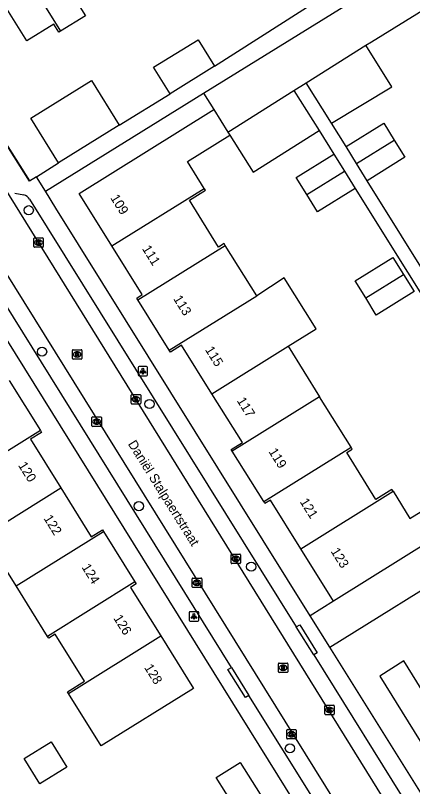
# Model space of a CAD drawing. Extents: x 159353 to 160616, y 385893 to 387321.
# Drawn here: x 159691.4 to 159733.4, y 385945.7 to 386027.3 of the extents above; entities that cross this region are included whole.
import ezdxf

# ---------------------------------------------------------------- set-up
doc = ezdxf.new("R2010")
doc.units = 0
for name, color, linetype in [('IMGEO_Boom', 7, 'Continuous'), ('IMGEO_Kolk', 7, 'Continuous'), ('IMGEO_Lichtpunt', 7, 'Continuous'), ('IMGEO_Muur', 7, 'Continuous'), ('IMGEO_Openbare_ruimte_label', 7, 'Continuous'), ('IMGEO_Pand', 7, 'Continuous'), ('IMGEO_Pand_nummerreeks', 7, 'Continuous'), ('IMGEO_Parkeervlak_open', 7, 'Continuous'), ('IMGEO_Rijbaan_lokaal_open', 7, 'Continuous'), ('IMGEO_Rioolput', 7, 'Continuous'), ('IMGEO_Voetpad_open', 7, 'Continuous')]:
    doc.layers.add(name, color=color, linetype=linetype)

msp = doc.modelspace()

# ---------------------------------------------------------------- linework, layer by layer
at = {"layer": 'IMGEO_Boom'}
for centre in [(159692.77, 386006.677), (159694.18, 385991.71), (159705.547, 385986.176), (159704.42, 385975.36), (159716.313, 385968.957), (159720.412, 385949.728)]:
    msp.add_circle(centre, 0.489, dxfattribs=at)
at = {"layer": 'IMGEO_Kolk'}
for p, q in [((159693.312, 386002.831), (159693.312, 386003.683)), ((159693.387, 386003.757), (159694.239, 386003.757)), ((159694.313, 386003.683), (159694.313, 386002.831)), ((159693.823, 386002.977), (159693.798, 386002.977)), ((159693.8, 386003.537), (159693.825, 386003.537)), ((159694.239, 386002.757), (159693.387, 386002.757)), ((159703.619, 385986.245), (159703.619, 385987.097)), ((159703.694, 385987.171), (159704.546, 385987.171)), ((159704.107, 385986.951), (159704.132, 385986.951)), ((159704.62, 385987.097), (159704.62, 385986.245)), ((159704.546, 385986.171), (159703.694, 385986.171)), ((159704.13, 385986.391), (159704.105, 385986.391)), ((159699.461, 385983.876), (159699.461, 385984.728)), ((159699.536, 385984.802), (159700.388, 385984.802)), ((159699.949, 385984.582), (159699.974, 385984.582)), ((159700.462, 385984.728), (159700.462, 385983.876)), ((159700.388, 385983.802), (159699.536, 385983.802)), ((159699.972, 385984.022), (159699.947, 385984.022)), ((159714.18, 385969.359), (159714.18, 385970.211)), ((159714.255, 385970.285), (159715.107, 385970.285)), ((159715.181, 385970.211), (159715.181, 385969.359)), ((159714.691, 385969.505), (159714.666, 385969.505)), ((159714.668, 385970.065), (159714.693, 385970.065)), ((159715.107, 385969.285), (159714.255, 385969.285)), ((159710.071, 385966.826), (159710.071, 385967.678)), ((159710.146, 385967.752), (159710.998, 385967.752)), ((159710.582, 385966.972), (159710.557, 385966.972)), ((159710.559, 385967.532), (159710.584, 385967.532)), ((159711.072, 385967.678), (159711.072, 385966.826)), ((159710.998, 385966.752), (159710.146, 385966.752)), ((159724.102, 385953.364), (159724.102, 385954.216)), ((159724.177, 385954.29), (159725.029, 385954.29)), ((159724.59, 385954.07), (159724.615, 385954.07)), ((159725.103, 385954.216), (159725.103, 385953.364)), ((159725.029, 385953.29), (159724.177, 385953.29)), ((159724.613, 385953.51), (159724.588, 385953.51)), ((159720.067, 385950.797), (159720.067, 385951.649)), ((159720.142, 385951.723), (159720.994, 385951.723)), ((159720.555, 385951.503), (159720.58, 385951.503)), ((159721.068, 385951.649), (159721.068, 385950.797)), ((159720.994, 385950.723), (159720.142, 385950.723)), ((159720.578, 385950.943), (159720.553, 385950.943))]:
    msp.add_line(p, q, dxfattribs=at)
for points in [[(159693.312, 386002.831), (159693.312, 386003.683)], [(159693.387, 386003.757), (159694.239, 386003.757)], [(159694.313, 386003.683), (159694.313, 386002.831)], [(159693.633, 386003.457), (159693.756, 386003.457), (159693.756, 386003.306), (159693.886, 386003.457), (159694.05, 386003.457), (159693.904, 386003.306), (159694.057, 386003.057), (159693.905, 386003.057), (159693.82, 386003.221), (159693.756, 386003.154), (159693.756, 386003.057), (159693.633, 386003.057), (159693.633, 386003.457)], [(159694.239, 386002.757), (159693.387, 386002.757)], [(159703.619, 385986.245), (159703.619, 385987.097)], [(159703.694, 385987.171), (159704.546, 385987.171)], [(159703.94, 385986.871), (159704.063, 385986.871), (159704.063, 385986.72), (159704.193, 385986.871), (159704.357, 385986.871), (159704.211, 385986.72), (159704.364, 385986.471), (159704.212, 385986.471), (159704.127, 385986.635), (159704.063, 385986.568), (159704.063, 385986.471), (159703.94, 385986.471), (159703.94, 385986.871)], [(159704.62, 385987.097), (159704.62, 385986.245)], [(159704.546, 385986.171), (159703.694, 385986.171)], [(159699.461, 385983.876), (159699.461, 385984.728)], [(159699.536, 385984.802), (159700.388, 385984.802)], [(159699.782, 385984.502), (159699.905, 385984.502), (159699.905, 385984.351), (159700.035, 385984.502), (159700.199, 385984.502), (159700.053, 385984.351), (159700.206, 385984.102), (159700.054, 385984.102), (159699.969, 385984.266), (159699.905, 385984.199), (159699.905, 385984.102), (159699.782, 385984.102), (159699.782, 385984.502)], [(159700.462, 385984.728), (159700.462, 385983.876)], [(159700.388, 385983.802), (159699.536, 385983.802)], [(159714.18, 385969.359), (159714.18, 385970.211)], [(159714.255, 385970.285), (159715.107, 385970.285)], [(159715.181, 385970.211), (159715.181, 385969.359)], [(159714.501, 385969.985), (159714.624, 385969.985), (159714.624, 385969.834), (159714.754, 385969.985), (159714.918, 385969.985), (159714.772, 385969.834), (159714.925, 385969.585), (159714.773, 385969.585), (159714.688, 385969.749), (159714.624, 385969.682), (159714.624, 385969.585), (159714.501, 385969.585), (159714.501, 385969.985)], [(159715.107, 385969.285), (159714.255, 385969.285)], [(159710.071, 385966.826), (159710.071, 385967.678)], [(159710.146, 385967.752), (159710.998, 385967.752)], [(159710.392, 385967.452), (159710.515, 385967.452), (159710.515, 385967.301), (159710.645, 385967.452), (159710.809, 385967.452), (159710.663, 385967.301), (159710.816, 385967.052), (159710.664, 385967.052), (159710.579, 385967.216), (159710.515, 385967.149), (159710.515, 385967.052), (159710.392, 385967.052), (159710.392, 385967.452)], [(159711.072, 385967.678), (159711.072, 385966.826)], [(159710.998, 385966.752), (159710.146, 385966.752)], [(159724.102, 385953.364), (159724.102, 385954.216)], [(159724.177, 385954.29), (159725.029, 385954.29)], [(159724.423, 385953.99), (159724.546, 385953.99), (159724.546, 385953.839), (159724.676, 385953.99), (159724.84, 385953.99), (159724.694, 385953.839), (159724.847, 385953.59), (159724.695, 385953.59), (159724.61, 385953.754), (159724.546, 385953.687), (159724.546, 385953.59), (159724.423, 385953.59), (159724.423, 385953.99)], [(159725.103, 385954.216), (159725.103, 385953.364)], [(159725.029, 385953.29), (159724.177, 385953.29)], [(159720.067, 385950.797), (159720.067, 385951.649)], [(159720.142, 385951.723), (159720.994, 385951.723)], [(159721.068, 385951.649), (159721.068, 385950.797)], [(159720.994, 385950.723), (159720.142, 385950.723)], [(159720.388, 385951.423), (159720.511, 385951.423), (159720.511, 385951.272), (159720.641, 385951.423), (159720.805, 385951.423), (159720.659, 385951.272), (159720.812, 385951.023), (159720.66, 385951.023), (159720.575, 385951.187), (159720.511, 385951.12), (159720.511, 385951.023), (159720.388, 385951.023), (159720.388, 385951.423)]]:
    msp.add_lwpolyline(points, dxfattribs=at)
for centre, start, end in [((159693.389, 386003.681), 91.55205, 178.44795), ((159693.389, 386003.681), 91.55205, 178.44795), ((159694.237, 386003.681), 1.55205, 88.44795), ((159694.237, 386003.681), 1.55205, 88.44795), ((159693.389, 386002.833), 181.55205, 268.44795), ((159693.389, 386002.833), 181.55205, 268.44795), ((159694.237, 386002.833), 271.55205, 358.44795), ((159694.237, 386002.833), 271.55205, 358.44795), ((159703.696, 385987.095), 91.55205, 178.44795), ((159703.696, 385987.095), 91.55205, 178.44795), ((159704.544, 385987.095), 1.55205, 88.44795), ((159704.544, 385987.095), 1.55205, 88.44795), ((159703.696, 385986.247), 181.55205, 268.44795), ((159703.696, 385986.247), 181.55205, 268.44795), ((159704.544, 385986.247), 271.55205, 358.44795), ((159704.544, 385986.247), 271.55205, 358.44795), ((159699.538, 385984.726), 91.55205, 178.44795), ((159699.538, 385984.726), 91.55205, 178.44795), ((159700.386, 385984.726), 1.55205, 88.44795), ((159700.386, 385984.726), 1.55205, 88.44795), ((159699.538, 385983.878), 181.55205, 268.44795), ((159699.538, 385983.878), 181.55205, 268.44795), ((159700.386, 385983.878), 271.55205, 358.44795), ((159700.386, 385983.878), 271.55205, 358.44795), ((159714.257, 385970.209), 91.55205, 178.44795), ((159714.257, 385970.209), 91.55205, 178.44795), ((159715.105, 385970.209), 1.55205, 88.44795), ((159715.105, 385970.209), 1.55205, 88.44795), ((159714.257, 385969.361), 181.55205, 268.44795), ((159714.257, 385969.361), 181.55205, 268.44795), ((159715.105, 385969.361), 271.55205, 358.44795), ((159715.105, 385969.361), 271.55205, 358.44795), ((159710.148, 385967.676), 91.55205, 178.44795), ((159710.148, 385967.676), 91.55205, 178.44795), ((159710.996, 385967.676), 1.55205, 88.44795), ((159710.996, 385967.676), 1.55205, 88.44795), ((159710.148, 385966.828), 181.55205, 268.44795), ((159710.148, 385966.828), 181.55205, 268.44795), ((159710.996, 385966.828), 271.55205, 358.44795), ((159710.996, 385966.828), 271.55205, 358.44795), ((159724.179, 385954.214), 91.55205, 178.44795), ((159724.179, 385954.214), 91.55205, 178.44795), ((159725.027, 385954.214), 1.55205, 88.44795), ((159725.027, 385954.214), 1.55205, 88.44795), ((159724.179, 385953.366), 181.55205, 268.44795), ((159724.179, 385953.366), 181.55205, 268.44795), ((159725.027, 385953.366), 271.55205, 358.44795), ((159725.027, 385953.366), 271.55205, 358.44795), ((159720.144, 385951.647), 91.55205, 178.44795), ((159720.144, 385951.647), 91.55205, 178.44795), ((159720.992, 385951.647), 1.55205, 88.44795), ((159720.992, 385951.647), 1.55205, 88.44795), ((159720.144, 385950.799), 181.55205, 268.44795), ((159720.144, 385950.799), 181.55205, 268.44795), ((159720.992, 385950.799), 271.55205, 358.44795), ((159720.992, 385950.799), 271.55205, 358.44795)]:
    msp.add_arc(centre, 0.0765, start, end, dxfattribs=at)
for centre, major_axis, ratio, start_param, end_param in [((159693.799, 386003.257), (-0.387, 0.002), 0.722429, 4.712389, 7.853982), ((159693.824, 386003.257), (-0.39, 0.002), 0.717154, 1.570796, 4.712389), ((159704.106, 385986.671), (-0.387, 0.002), 0.722429, 4.712389, 7.853982), ((159704.131, 385986.671), (-0.39, 0.002), 0.717154, 1.570796, 4.712389), ((159699.948, 385984.302), (-0.387, 0.002), 0.722429, 4.712389, 7.853982), ((159699.973, 385984.302), (-0.39, 0.002), 0.717154, 1.570796, 4.712389), ((159714.667, 385969.785), (-0.387, 0.002), 0.722429, 4.712389, 7.853982), ((159714.692, 385969.785), (-0.39, 0.002), 0.717154, 1.570796, 4.712389), ((159710.558, 385967.252), (-0.387, 0.002), 0.722429, 4.712389, 7.853982), ((159710.583, 385967.252), (-0.39, 0.002), 0.717154, 1.570796, 4.712389), ((159724.589, 385953.79), (-0.387, 0.002), 0.722429, 4.712389, 7.853982), ((159724.614, 385953.79), (-0.39, 0.002), 0.717154, 1.570796, 4.712389), ((159720.554, 385951.223), (-0.387, 0.002), 0.722429, 4.712389, 7.853982), ((159720.579, 385951.223), (-0.39, 0.002), 0.717154, 1.570796, 4.712389)]:
    msp.add_ellipse(centre, major_axis=major_axis, ratio=ratio, start_param=start_param, end_param=end_param, dxfattribs=at)
at = {"layer": 'IMGEO_Lichtpunt'}
for p, q in [((159704.345, 385990.054), (159704.345, 385989.247)), ((159704.345, 385990.054), (159704.345, 385989.247)), ((159705.247, 385990.149), (159704.439, 385990.149)), ((159705.247, 385990.149), (159704.439, 385990.149)), ((159705.341, 385989.247), (159705.341, 385990.054)), ((159705.341, 385989.247), (159705.341, 385990.054)), ((159704.439, 385989.153), (159705.247, 385989.153)), ((159704.439, 385989.153), (159705.247, 385989.153)), ((159709.758, 385964.093), (159709.758, 385963.286)), ((159709.758, 385964.093), (159709.758, 385963.286)), ((159710.66, 385964.188), (159709.852, 385964.188)), ((159710.66, 385964.188), (159709.852, 385964.188)), ((159710.754, 385963.286), (159710.754, 385964.093)), ((159710.754, 385963.286), (159710.754, 385964.093)), ((159709.852, 385963.192), (159710.66, 385963.192)), ((159709.852, 385963.192), (159710.66, 385963.192))]:
    msp.add_line(p, q, dxfattribs=at)
for points in [[(159704.719, 385989.718), (159704.758, 385989.69), (159704.57, 385989.428), (159704.532, 385989.455), (159704.719, 385989.718)], [(159704.821, 385989.67), (159704.868, 385989.67), (159704.868, 385989.348), (159704.821, 385989.348), (159704.821, 385989.67)], [(159704.931, 385989.69), (159704.969, 385989.717), (159705.156, 385989.455), (159705.117, 385989.427), (159704.931, 385989.69)], [(159710.132, 385963.757), (159710.171, 385963.729), (159709.983, 385963.467), (159709.945, 385963.494), (159710.132, 385963.757)], [(159710.234, 385963.709), (159710.281, 385963.709), (159710.281, 385963.387), (159710.234, 385963.387), (159710.234, 385963.709)], [(159710.344, 385963.729), (159710.382, 385963.756), (159710.569, 385963.494), (159710.53, 385963.466), (159710.344, 385963.729)]]:
    msp.add_lwpolyline(points, dxfattribs=at)
for centre in [(159704.844, 385989.852), (159710.257, 385963.891)]:
    msp.add_circle(centre, 0.0994, dxfattribs=at)
for centre, start, end in [((159704.439, 385990.054), 90, 180), ((159704.439, 385990.054), 90, 180), ((159705.247, 385990.054), 0, 90), ((159705.247, 385990.054), 0, 90), ((159704.439, 385989.247), 180, 270), ((159704.439, 385989.247), 180, 270), ((159705.247, 385989.247), 270, 0), ((159705.247, 385989.247), 270, 360), ((159709.852, 385964.093), 90, 180), ((159709.852, 385964.093), 90, 180), ((159710.66, 385964.093), 0, 90), ((159710.66, 385964.093), 0, 90), ((159709.852, 385963.286), 180, 270), ((159709.852, 385963.286), 180, 270), ((159710.66, 385963.286), 270, 0), ((159710.66, 385963.286), 270, 360)]:
    msp.add_arc(centre, 0.0946, start, end, dxfattribs=at)
at = {"layer": 'IMGEO_Muur'}
msp.add_lwpolyline([(159676.499, 386035.726), (159692.838, 386009.794)], dxfattribs=at)
at = {"layer": 'IMGEO_Pand'}
for points in [[(159696.144, 386025.636), (159695.953, 386025.516), (159695.412, 386026.381), (159692.572, 386024.604), (159688.668, 386030.843), (159686.251, 386029.331), (159682.354, 386035.559), (159687.801, 386038.964)], [(159687.801, 386038.964), (159696.144, 386025.636)], [(159696.906, 386035.948), (159694.342, 386034.344), (159698.765, 386027.275), (159696.144, 386025.636)], [(159707.722, 386019.015), (159705.988, 386021.823), (159710.701, 386024.734), (159712.435, 386021.927)], [(159712.435, 386021.927), (159707.722, 386019.015)], [(159695.905, 386011.714), (159692.99, 386016.431), (159699.422, 386020.406), (159702.337, 386015.688)], [(159701.573, 386002.905), (159698.121, 386008.449), (159712.358, 386017.329)], [(159712.358, 386017.329), (159713.852, 386014.956)], [(159702.337, 386015.688), (159695.905, 386011.714)], [(159726.347, 386013.429), (159730.332, 386015.904), (159731.456, 386014.095)], [(159711.345, 386008.993), (159709.58, 386011.831), (159714.064, 386014.619)], [(159713.852, 386014.956), (159714.064, 386014.619)], [(159727.472, 386011.619), (159731.456, 386014.095)], [(159731.456, 386014.095), (159732.581, 386012.285), (159728.596, 386009.809)], [(159727.472, 386011.619), (159726.347, 386013.429)], [(159722.197, 386008.34), (159721.075, 386010.152), (159725.066, 386012.623)], [(159725.066, 386012.623), (159726.188, 386010.811)], [(159728.596, 386009.809), (159727.472, 386011.619)], [(159722.197, 386008.34), (159726.188, 386010.811)], [(159726.188, 386010.811), (159727.309, 386008.999)], [(159701.573, 386002.905), (159711.345, 386008.993)], [(159713.572, 386002.958), (159713.456, 386003.144), (159712.858, 386002.772), (159709.767, 386007.743), (159711.466, 386008.8), (159711.345, 386008.993)], [(159727.309, 386008.999), (159723.318, 386006.528), (159722.197, 386008.34)], [(159704.315, 385997.19), (159704.197, 385997.379), (159704.777, 385997.76), (159701.573, 386002.905)], [(159704.315, 385997.19), (159713.572, 386002.958)], [(159716.891, 385997.631), (159713.572, 386002.958)], [(159728.429, 385997.398), (159727.305, 385999.211), (159731.308, 386001.692), (159732.432, 385999.879)], [(159732.432, 385999.879), (159733.556, 385998.065), (159729.553, 385995.584), (159728.429, 385997.398)], [(159728.429, 385997.398), (159732.432, 385999.879)], [(159720.223, 385992.284), (159723.171, 385994.121), (159719.794, 385999.54), (159716.891, 385997.631)], [(159707.64, 385991.867), (159704.315, 385997.19)], [(159707.64, 385991.867), (159716.891, 385997.631)], [(159712.158, 385987.259), (159708.951, 385992.406), (159707.766, 385991.665), (159707.64, 385991.867)], [(159712.158, 385987.259), (159720.223, 385992.284)], [(159720.223, 385992.284), (159723.551, 385986.943)], [(159690.706, 385988.673), (159694.003, 385983.38)], [(159714.307, 385981.183), (159714.197, 385981.36), (159715.376, 385982.096), (159712.158, 385987.259)], [(159723.551, 385986.943), (159714.307, 385981.183)], [(159726.883, 385981.596), (159723.551, 385986.943)], [(159694.003, 385983.38), (159684.76, 385977.619)], [(159694.003, 385983.38), (159694.133, 385983.172), (159692.958, 385982.44), (159696.161, 385977.302)], [(159717.641, 385975.838), (159714.307, 385981.183)], [(159717.641, 385975.838), (159726.883, 385981.596)], [(159731.319, 385976.937), (159731.21, 385977.113), (159729.504, 385976.056), (159726.418, 385981.026), (159727.009, 385981.393), (159726.883, 385981.596)], [(159688.093, 385972.273), (159696.161, 385977.302)], [(159696.161, 385977.302), (159699.391, 385972.121), (159700.565, 385972.856), (159700.666, 385972.682)], [(159721.556, 385970.854), (159731.319, 385976.937)], [(159731.319, 385976.937), (159733.106, 385974.053), (159737.6, 385976.854)], [(159721.556, 385970.854), (159718.347, 385976.003), (159717.769, 385975.633), (159717.641, 385975.838)], [(159739.263, 385974.184), (159725.011, 385965.31)], [(159691.427, 385966.923), (159700.666, 385972.682)], [(159700.666, 385972.682), (159703.999, 385967.336)], [(159691.427, 385966.923), (159688.093, 385972.273)], [(159725.011, 385965.31), (159721.556, 385970.854)], [(159703.999, 385967.336), (159694.759, 385961.577)], [(159703.999, 385967.336), (159704.125, 385967.134), (159703.549, 385966.769), (159706.743, 385961.623)], [(159694.759, 385961.577), (159691.427, 385966.923)], [(159696.983, 385955.539), (159696.873, 385955.715), (159698.661, 385956.829), (159695.565, 385961.797), (159694.886, 385961.374), (159694.759, 385961.577)], [(159706.743, 385961.623), (159710.197, 385956.058), (159700.437, 385949.995), (159696.983, 385955.539)], [(159696.983, 385955.539), (159706.743, 385961.623)], [(159738.519, 385955.993), (159735.503, 385954.102), (159732.449, 385958.973), (159729.907, 385957.38), (159736.569, 385946.668), (159738.635, 385947.938), (159739.432, 385946.69), (159743.059, 385948.937), (159742.6, 385949.696)], [(159695.153, 385950.416), (159696.811, 385947.749), (159693.961, 385945.976), (159692.3, 385948.636), (159695.153, 385950.416)], [(159712.662, 385939.89), (159715.667, 385941.768), (159712.62, 385946.644), (159715.147, 385948.223), (159721.911, 385937.512), (159719.777, 385936.172), (159720.578, 385934.892), (159717.167, 385932.756)]]:
    msp.add_lwpolyline(points, dxfattribs=at)
at = {"layer": 'IMGEO_Parkeervlak_open'}
for points in [[(159724.8, 386015.886), (159731.199, 386019.749), (159728.436, 386024.138)], [(159714.064, 386014.619), (159716.524, 386010.711), (159723.504, 386015.104)]]:
    msp.add_lwpolyline(points, dxfattribs=at)
at = {"layer": 'IMGEO_Rijbaan_lokaal_open'}
for points in [[(159711.277, 386019.075), (159743.822, 386039.222)], [(159728.436, 386024.138), (159729.047, 386024.522), (159746.307, 386035.207)], [(159722.112, 386020.156), (159728.436, 386024.138)], [(159720.831, 386019.35), (159722.112, 386020.156)], [(159713.852, 386014.956), (159720.831, 386019.35)], [(159711.277, 386019.075), (159712.358, 386017.329)], [(159690.064, 386009.27), (159733.253, 385939.657)], [(159729.51, 385937.17), (159689.128, 386002.021)], [(159724.622, 385960.426), (159753.911, 385978.646)], [(159725.011, 385965.31), (159722.539, 385963.769)], [(159724.622, 385960.426), (159722.539, 385963.769)]]:
    msp.add_lwpolyline(points, dxfattribs=at)
at = {"layer": 'IMGEO_Rioolput'}
for p, q in [((159697.394, 385990.995), (159697.394, 385991.847)), ((159697.469, 385991.921), (159698.321, 385991.921)), ((159697.882, 385991.701), (159697.907, 385991.701)), ((159698.395, 385991.847), (159698.395, 385990.995)), ((159698.321, 385990.921), (159697.469, 385990.921)), ((159697.905, 385991.141), (159697.88, 385991.141)), ((159719.188, 385957.834), (159719.188, 385958.686)), ((159719.263, 385958.76), (159720.115, 385958.76)), ((159719.699, 385957.98), (159719.674, 385957.98)), ((159719.676, 385958.54), (159719.701, 385958.54)), ((159720.189, 385958.686), (159720.189, 385957.834)), ((159720.115, 385957.76), (159719.263, 385957.76))]:
    msp.add_line(p, q, dxfattribs=at)
for points in [[(159697.394, 385990.995), (159697.394, 385991.847)], [(159697.469, 385991.921), (159698.321, 385991.921)], [(159697.983, 385991.619), (159697.731, 385991.621), (159697.731, 385991.221)], [(159697.909, 385991.54), (159697.855, 385991.54), (159697.855, 385991.459)], [(159697.855, 385991.459), (159697.907, 385991.459)], [(159698.395, 385991.847), (159698.395, 385990.995)], [(159698.321, 385990.921), (159697.469, 385990.921)], [(159697.731, 385991.221), (159697.855, 385991.221), (159697.855, 385991.383), (159697.866, 385991.383)], [(159697.913, 385991.354), (159697.984, 385991.221), (159698.124, 385991.221), (159698.059, 385991.347)], [(159719.188, 385957.834), (159719.188, 385958.686)], [(159719.263, 385958.76), (159720.115, 385958.76)], [(159719.777, 385958.458), (159719.525, 385958.46), (159719.525, 385958.06)], [(159719.525, 385958.06), (159719.649, 385958.06), (159719.649, 385958.222), (159719.66, 385958.222)], [(159719.703, 385958.379), (159719.649, 385958.379), (159719.649, 385958.298)], [(159719.649, 385958.298), (159719.701, 385958.298)], [(159719.707, 385958.193), (159719.778, 385958.06), (159719.918, 385958.06), (159719.853, 385958.186)], [(159720.189, 385958.686), (159720.189, 385957.834)], [(159720.115, 385957.76), (159719.263, 385957.76)]]:
    msp.add_lwpolyline(points, dxfattribs=at)
for centre, radius, start, end in [((159697.471, 385991.845), 0.0765, 91.55205, 178.44795), ((159697.471, 385991.845), 0.0765, 91.55205, 178.44795), ((159697.891, 385991.648), 0.19, 274.7715, 282.96867), ((159697.915, 385991.444), 0.0964, 77.00612, 93.18647), ((159697.929, 385991.501), 0.0378, 276.66336, 79.67722), ((159697.982, 385991.509), 0.109, 350.36119, 89.41601), ((159697.98, 385991.509), 0.112, 277.58423, 350.98172), ((159698.319, 385991.845), 0.0765, 1.55205, 88.44795), ((159698.319, 385991.845), 0.0765, 1.55205, 88.44795), ((159697.471, 385990.997), 0.0765, 181.55205, 268.44795), ((159697.471, 385990.997), 0.0765, 181.55205, 268.44795), ((159697.865, 385991.33), 0.0533, 26.02933, 88.69889), ((159697.964, 385991.294), 0.108, 29.51342, 73.79051), ((159698.319, 385990.997), 0.0765, 271.55205, 358.44795), ((159698.319, 385990.997), 0.0765, 271.55205, 358.44795), ((159719.265, 385958.684), 0.0765, 91.55205, 178.44795), ((159719.265, 385958.684), 0.0765, 91.55205, 178.44795), ((159719.659, 385958.169), 0.0533, 26.02933, 88.69889), ((159719.685, 385958.487), 0.19, 274.7715, 282.96867), ((159719.709, 385958.283), 0.0964, 77.00612, 93.18647), ((159719.723, 385958.34), 0.0378, 276.66336, 79.67722), ((159719.776, 385958.348), 0.109, 350.36119, 89.41601), ((159719.774, 385958.348), 0.112, 277.58423, 350.98172), ((159719.758, 385958.133), 0.108, 29.51342, 73.79051), ((159720.113, 385958.684), 0.0765, 1.55205, 88.44795), ((159720.113, 385958.684), 0.0765, 1.55205, 88.44795), ((159719.265, 385957.836), 0.0765, 181.55205, 268.44795), ((159719.265, 385957.836), 0.0765, 181.55205, 268.44795), ((159720.113, 385957.836), 0.0765, 271.55205, 358.44795), ((159720.113, 385957.836), 0.0765, 271.55205, 358.44795)]:
    msp.add_arc(centre, radius, start, end, dxfattribs=at)
for centre, major_axis, ratio, start_param, end_param in [((159697.881, 385991.421), (-0.387, 0.002), 0.722429, 4.712389, 7.853982), ((159697.906, 385991.421), (-0.39, 0.002), 0.717154, 1.570796, 4.712389), ((159719.675, 385958.26), (-0.387, 0.002), 0.722429, 4.712389, 7.853982), ((159719.7, 385958.26), (-0.39, 0.002), 0.717154, 1.570796, 4.712389)]:
    msp.add_ellipse(centre, major_axis=major_axis, ratio=ratio, start_param=start_param, end_param=end_param, dxfattribs=at)
at = {"layer": 'IMGEO_Voetpad_open'}
for points in [[(159726.677, 385934.766), (159683.777, 386003.638), (159684.463, 386004.075), (159676.127, 386017.48), (159664.396, 386036.344), (159664.447, 386037.85), (159665.019, 386042.984)], [(159693.588, 386010.224), (159692.861, 386009.756), (159676.499, 386035.726)], [(159712.435, 386021.927), (159733.186, 386035.211)], [(159724.8, 386015.886), (159722.112, 386020.156)], [(159720.831, 386019.35), (159723.504, 386015.104)], [(159694.532, 386008.709), (159711.277, 386019.075)], [(159702.337, 386015.688), (159707.722, 386019.015)], [(159723.504, 386015.104), (159725.066, 386012.623)], [(159726.347, 386013.429), (159724.8, 386015.886)], [(159693.588, 386010.224), (159695.905, 386011.714)], [(159694.532, 386008.709), (159693.588, 386010.224)], [(159739.66, 385992.052), (159728.596, 386009.809)], [(159722.539, 385963.769), (159695.653, 386006.911), (159694.532, 386008.709)], [(159727.309, 386008.999), (159738.387, 385991.268)], [(159691.296, 386008.497), (159692.239, 386008.296)], [(159692.854, 386007.849), (159721.084, 385962.578)], [(159714.229, 385958.291), (159689.162, 385998.525)], [(159721.084, 385962.578), (159721.452, 385962.783), (159723.277, 385959.824), (159722.95, 385959.611)], [(159722.95, 385959.611), (159721.084, 385962.578)], [(159736.793, 385940.979), (159724.622, 385960.426)], [(159722.95, 385959.611), (159733.348, 385942.906)], [(159716.071, 385955.325), (159715.692, 385955.092), (159713.835, 385958.065), (159714.229, 385958.291)], [(159714.229, 385958.291), (159716.071, 385955.325)], [(159726.497, 385938.638), (159716.071, 385955.325)]]:
    msp.add_lwpolyline(points, dxfattribs=at)
msp.add_arc((159692.055, 386007.396), 0.919, 29.55542, 78.42308, dxfattribs=at)

# ---------------------------------------------------------------- texts
at = {"layer": 'IMGEO_Openbare_ruimte_label'}
msp.add_text('Daniël Stalpaertstraat', height=1, rotation=302.00538, dxfattribs=at).set_placement((159703.231, 385981.95))
at = {"layer": 'IMGEO_Pand_nummerreeks'}
for s, rotation, p in [('109', 301.90781, (159701.374, 386007.994)), ('111', 301.93564, (159704.729, 386002.612)), ('113', 301.93564, (159708.032, 385997.313)), ('115', 301.93646, (159711.393, 385991.921)), ('117', 301.93564, (159714.754, 385986.528)), ('119', 301.93564, (159718.114, 385981.139)), ('120', 301.92235, (159691.612, 385979.687)), ('121', 301.93092, (159721.424, 385975.83)), ('122', 301.94006, (159694.308, 385974.075)), ('123', 301.93092, (159724.692, 385970.585)), ('124', 301.92235, (159698.332, 385968.9)), ('126', 301.92235, (159701.693, 385963.506)), ('128', 301.8288, (159704.955, 385958.284))]:
    msp.add_text(s, height=1, rotation=rotation, dxfattribs=at).set_placement(p)

doc.saveas('drawing.dxf')
